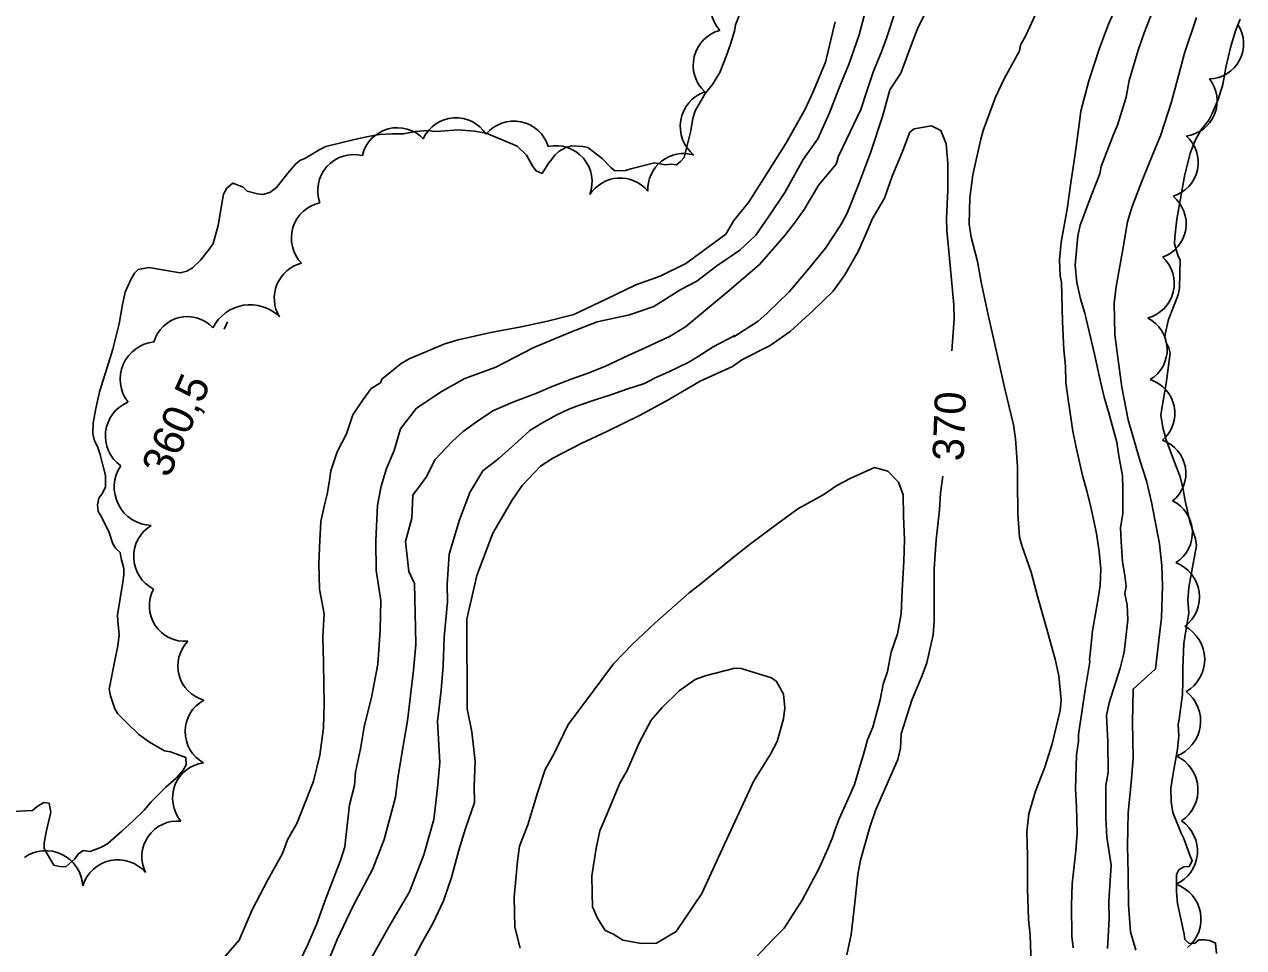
# Model space of a CAD drawing. Extents: x 287698 to 290158, y 5234163 to 5237182.
# Drawn here: x 288524.6 to 288641.9, y 5235240.4 to 5235329.1 of the extents above; entities that cross this region are included whole.
import ezdxf

# ---------------------------------------------------------------- set-up
doc = ezdxf.new("R2010")
doc.units = 0
for name, color, linetype in [('Niveau 1', 7, 'Continuous'), ('Niveau 2', 7, 'Continuous'), ('Niveau 3', 7, 'Continuous'), ('Niveau 4', 7, 'Continuous'), ('Niveau 44', 7, 'Continuous')]:
    doc.layers.add(name, color=color, linetype=linetype)

msp = doc.modelspace()

# ---------------------------------------------------------------- linework, layer by layer
at = {"layer": 'Niveau 1'}
for points in [[(288561.91, 5235239.04), (288562.8, 5235240.76), (288563.94, 5235242.74), (288564.94, 5235244.85), (288565.69, 5235247.08), (288566.42, 5235249.72), (288567.04, 5235251.82), (288567.9, 5235254.32), (288567.87, 5235255.89), (288567.97, 5235258.24), (288567.64, 5235261.11), (288567.21, 5235263.33), (288567.17, 5235271.95), (288568.14, 5235276.15), (288569.69, 5235280.2), (288571.56, 5235283.44), (288572.49, 5235284.79), (288574.26, 5235286.66), (288575.45, 5235287.42), (288578.19, 5235288.84), (288580.65, 5235290), (288583.79, 5235291.53), (288586.44, 5235292.98), (288589.63, 5235294.83), (288592.74, 5235296.23), (288593.65, 5235296.89), (288596.38, 5235298.26), (288598.31, 5235299.6), (288600.49, 5235301.61), (288602.43, 5235303.48), (288603.57, 5235305.07), (288604.83, 5235307.31), (288605.47, 5235308.76), (288606.21, 5235310.47), (288607.36, 5235312.45), (288608.1, 5235314.56), (288609.1, 5235316.94), (288609.81, 5235318.77), (288610.23, 5235319.12), (288611.91, 5235319.4), (288612.8, 5235318.95), (288613.3, 5235317.67), (288613.47, 5235315.81), (288613.46, 5235313.21), (288613.34, 5235310.49), (288613.38, 5235309.32), (288613.69, 5235305.97), (288614.05, 5235302.18), (288614.09, 5235300.84), (288613.85, 5235297.76)], [(288612.99, 5235285.68), (288612.76, 5235284.05), (288612.66, 5235282.47), (288612.33, 5235279.58), (288612.16, 5235276.78), (288612.16, 5235275.19), (288612.15, 5235271.76), (288612.06, 5235270.45), (288611.45, 5235267.75), (288611, 5235266.52), (288610, 5235264.15), (288608.98, 5235260.9), (288608.91, 5235259.54), (288608.65, 5235258.43), (288607.73, 5235256.32), (288606.52, 5235253.55), (288605.95, 5235251.95), (288605.06, 5235248.77), (288604.81, 5235247.37), (288604.51, 5235244.65), (288604.18, 5235241.62), (288603.75, 5235239.66)]]:
    msp.add_lwpolyline(points, dxfattribs=at)
at = {"layer": 'Niveau 2'}
for points in [[(288635.82, 5235348.16), (288635.44, 5235346.6), (288634.77, 5235343.73), (288634.07, 5235340.99), (288633.69, 5235340.04), (288632.52, 5235337.37), (288631.44, 5235334.9), (288630.05, 5235331.71), (288628.93, 5235329.16), (288628.08, 5235326.87), (288627.04, 5235323.71), (288626.27, 5235320.82), (288626.08, 5235319.31), (288625.72, 5235316.7), (288625.32, 5235313.9), (288624.95, 5235311.38), (288624.38, 5235308.2), (288624.23, 5235306.49), (288624.29, 5235304.97), (288624.4, 5235304.35)], [(288550.47, 5235237.71), (288551.84, 5235240.6), (288552.71, 5235242.57), (288553.59, 5235245.07), (288555.05, 5235248.84), (288555.43, 5235250.03), (288555.54, 5235250.94), (288555.87, 5235254.09), (288556.36, 5235255.93), (288556.46, 5235257.24), (288556.95, 5235259.47), (288557.3, 5235261.57), (288558.02, 5235264.58), (288558.62, 5235267.6), (288558.82, 5235270.88), (288558.9, 5235273.75), (288558.45, 5235276.61), (288558.4, 5235279.49), (288558.59, 5235282.9), (288558.94, 5235284.73), (288559.44, 5235286.43), (288560.19, 5235288.15), (288560.8, 5235290.25), (288562.33, 5235292.24), (288564.79, 5235293.86), (288566.99, 5235295.08), (288569.98, 5235296.18), (288573.61, 5235298.08), (288575.94, 5235299.04), (288577.24, 5235299.59), (288579.71, 5235300.55), (288582.83, 5235301.21), (288585.18, 5235302.03), (288587.76, 5235303.65), (288589.31, 5235304.46), (288591.25, 5235305.94), (288593.45, 5235307.42), (288594.99, 5235308.88), (288596.27, 5235310.74), (288597.79, 5235312.99), (288599.56, 5235316.16), (288600.96, 5235318.15), (288602.09, 5235320.65), (288602.96, 5235322.89), (288603.97, 5235325.4), (288604.95, 5235328.16), (288605.93, 5235331.97)], [(288610.54, 5235328.72), (288611.73, 5235331.14)], [(288633.75, 5235331.89), (288632.37, 5235328.33), (288631.8, 5235326.66), (288630.92, 5235323.74), (288630.63, 5235322.15), (288629.8, 5235319.45), (288629.4, 5235318.56), (288628.23, 5235315.49), (288628.09, 5235314.77), (288627.33, 5235312.82), (288626.22, 5235309.83), (288625.97, 5235308.8), (288625.73, 5235305.99), (288625.9, 5235304.33), (288626.23, 5235302.74), (288626.67, 5235301.36)], [(288553.43, 5235238.09), (288554.68, 5235241.12), (288556.19, 5235244.29), (288558.08, 5235247.86), (288559.21, 5235250.75), (288560.31, 5235254.82), (288560.54, 5235256.66), (288561, 5235259.55), (288561.47, 5235262.17), (288562.04, 5235267.02), (288562.25, 5235269.5), (288562.22, 5235271.07), (288562.14, 5235275.38), (288561.59, 5235276.54), (288561.28, 5235279.42), (288561.88, 5235281.65), (288561.97, 5235283.87), (288563.25, 5235285.6), (288564.13, 5235287.31), (288565.8, 5235289.05), (288566.83, 5235289.98), (288568.12, 5235290.92), (288569.67, 5235291.99), (288571.61, 5235292.82), (288573.83, 5235293.64), (288575.39, 5235294.32), (288577.2, 5235295.02), (288578.76, 5235295.57), (288580.45, 5235296.25), (288582.78, 5235297.35), (288584.34, 5235298.03), (288586.68, 5235299.12), (288588.23, 5235300.06), (288590.16, 5235301.67), (288592.22, 5235303.41), (288595.31, 5235306.02), (288596.46, 5235307.35), (288597.74, 5235308.81), (288598.76, 5235310.14), (288599.65, 5235311.33), (288601.05, 5235313.71), (288602.71, 5235315.7), (288602.96, 5235316.49), (288603.71, 5235318.07), (288605.09, 5235320.97), (288605.72, 5235322.81), (288606.33, 5235324.66), (288607.09, 5235326.5), (288607.58, 5235327.82), (288608.44, 5235330.45)], [(288621.89, 5235330.03), (288621.01, 5235328.14), (288620.47, 5235327.14), (288620.38, 5235326.61), (288619.98, 5235325.9)], [(288542.58, 5235237.94), (288545.26, 5235241.08), (288546.52, 5235243.97), (288548.03, 5235246.87), (288549.42, 5235249.39), (288549.92, 5235250.7), (288550.81, 5235252.29), (288551.8, 5235254.79), (288552.43, 5235256.37), (288553.03, 5235258.87), (288553.37, 5235261.49), (288553.45, 5235263.84), (288553.42, 5235265.67), (288553.38, 5235267.76), (288553.33, 5235270.24), (288553.43, 5235272.46), (288552.98, 5235274.82), (288552.94, 5235277.3), (288553.02, 5235279.52), (288553.12, 5235281.35), (288553.49, 5235282.93), (288553.73, 5235283.97), (288553.96, 5235285.29), (288554.08, 5235286.2), (288554.7, 5235288.04), (288555.58, 5235289.76), (288556.2, 5235291.6), (288557.21, 5235293.06), (288557.98, 5235294.12), (288558.88, 5235294.67), (288558.99, 5235295.02), (288560.84, 5235296.52), (288561.63, 5235296.97), (288565.07, 5235298.44), (288566.34, 5235298.81), (288569.5, 5235299.5), (288572.39, 5235300.06), (288574.94, 5235300.6), (288577.48, 5235301.26), (288580.59, 5235302.72), (288583.44, 5235304.09), (288585.77, 5235304.92), (288588.24, 5235306.14), (288589.92, 5235307.36), (288592.11, 5235308.96), (288592.86, 5235310.28), (288594.27, 5235312.01), (288595.8, 5235314.39), (288597.87, 5235317.68), (288599.73, 5235321), (288600.46, 5235322.6), (288601.7, 5235325.52), (288602.64, 5235329.4)], [(288557.99, 5235239.36), (288559.63, 5235242.27), (288561.66, 5235245.7), (288563.03, 5235249.26), (288564.01, 5235252.67), (288564.34, 5235255.69), (288564.56, 5235258.17), (288564.35, 5235262.09), (288564.69, 5235265.11), (288564.91, 5235267.46), (288564.99, 5235270.21), (288565.31, 5235273.61), (288565.28, 5235275.31), (288565.48, 5235278.19), (288566.47, 5235281.48), (288567.47, 5235284.11), (288568.73, 5235286.22), (288570.28, 5235287.43), (288572.08, 5235289.04), (288573.24, 5235290.1), (288574.4, 5235290.78), (288575.83, 5235291.59), (288577, 5235292.13), (288578.03, 5235292.54), (288579.72, 5235293.11), (288581.02, 5235293.52), (288582.58, 5235294.07), (288584.27, 5235294.62), (288585.31, 5235295.17), (288586.61, 5235295.72), (288588.55, 5235296.67), (288589.45, 5235297.21), (288590.88, 5235298.15), (288592.96, 5235299.24), (288592.88, 5235299.09), (288595.23, 5235300.61), (288596.08, 5235301.39), (288598.19, 5235303.44), (288599.96, 5235305.51), (288601.68, 5235307.63), (288603.18, 5235309.88), (288603.77, 5235311), (288604.97, 5235313.96), (288606.05, 5235316.88), (288607.17, 5235320.29), (288607.88, 5235322.86), (288608.96, 5235324.45), (288610.07, 5235327.48), (288610.54, 5235328.72)], [(288637.41, 5235329.82), (288636.25, 5235326.39), (288635.7, 5235324.32), (288634.99, 5235321.7), (288633.95, 5235318.42), (288633.2, 5235316.66), (288632.1, 5235313.98), (288631.2, 5235311.62), (288630.77, 5235310.17), (288630.32, 5235307.49), (288629.66, 5235303.95), (288629.49, 5235302.34), (288629.55, 5235299.33), (288629.78, 5235297.58), (288630.2, 5235294.26), (288630.84, 5235291.11), (288631.95, 5235287.22), (288632.58, 5235285.25), (288633.07, 5235283.2), (288633.85, 5235279.18), (288634.08, 5235277.07)], [(288619.98, 5235325.9), (288618.88, 5235323.93), (288618.07, 5235322.16), (288616.86, 5235318.96), (288616.6, 5235317.98), (288615.89, 5235314.69), (288615.59, 5235312.48)], [(288615.59, 5235312.48), (288615.52, 5235309.97), (288615.71, 5235308.69), (288616.31, 5235306.34), (288616.69, 5235304.36), (288617.36, 5235301.22), (288618.17, 5235297.54), (288618.94, 5235294.09), (288619.8, 5235290.62), (288619.97, 5235289.28), (288620.17, 5235286.62), (288620.17, 5235285.2), (288620.21, 5235282.04), (288620.37, 5235279.83), (288620.63, 5235278.93), (288621.5, 5235276.46), (288622.14, 5235274.01), (288622.93, 5235271.21), (288623.81, 5235268.09), (288624.14, 5235266.48), (288624.37, 5235264.14), (288624.27, 5235263.16), (288623.52, 5235259.95), (288622.8, 5235257.69), (288621.9, 5235255.41), (288621.28, 5235253.23), (288621.08, 5235251.5), (288621.14, 5235249.23), (288621.15, 5235245.99), (288621.22, 5235243.06), (288621.38, 5235241.53), (288621.48, 5235238.81)], [(288624.4, 5235304.35), (288624.52, 5235300.58), (288624.64, 5235297.86), (288624.79, 5235296.29), (288624.82, 5235294.72), (288625.04, 5235293.08), (288625.51, 5235290.01), (288625.79, 5235288.6), (288626.43, 5235285.76), (288626.86, 5235284.27), (288627.27, 5235282.59), (288627.78, 5235280.17), (288628.05, 5235278.45), (288628.2, 5235276.78), (288628.14, 5235275.19), (288627.9, 5235273.73), (288627.39, 5235270.81), (288627.18, 5235268.61), (288627.11, 5235268.1), (288627.14, 5235267.84)], [(288626.67, 5235301.36), (288627.6, 5235297.44), (288628.06, 5235295.23), (288628.53, 5235293.28), (288628.93, 5235291.87), (288629.72, 5235288.96), (288629.93, 5235287.65), (288630.28, 5235285.74), (288630.32, 5235284.47), (288630.31, 5235282.06), (288630.1, 5235280.75), (288630.16, 5235279.4), (288630.29, 5235277.47), (288630.5, 5235276.15), (288630.62, 5235275.12), (288630.5, 5235274.41), (288630.68, 5235273.61)], [(288572.3, 5235240.28), (288571.78, 5235242.33), (288571.73, 5235245.19), (288572.06, 5235248.67), (288572.24, 5235250.1), (288573.03, 5235252.16), (288573.99, 5235255.23), (288574.7, 5235257.47), (288575.55, 5235258.95), (288576.94, 5235261.82), (288578.51, 5235263.9), (288581.3, 5235267.64), (288583.09, 5235269.51), (288585.27, 5235271.56), (288588.57, 5235274.46), (288589.72, 5235275.36), (288593.12, 5235278.12), (288594.47, 5235279.2), (288596.37, 5235280.59), (288599.03, 5235282.54), (288601.54, 5235283.93), (288602.79, 5235284.81), (288604.07, 5235285.47), (288606.41, 5235286.53), (288607.68, 5235286.18), (288608.73, 5235285.12), (288609.16, 5235283.9), (288609.19, 5235281.86), (288609.29, 5235279.59), (288609.22, 5235277.49), (288609.06, 5235274.74), (288608.97, 5235272.46), (288608.62, 5235270.53), (288608.03, 5235268.76), (288607.65, 5235266.92), (288607.26, 5235265.69), (288606.95, 5235264.19), (288606.26, 5235261.55), (288605.74, 5235260.35), (288605.35, 5235258.91), (288604.97, 5235257.67), (288604.48, 5235256.04), (288603.88, 5235254.66), (288603.58, 5235254.02), (288603.02, 5235252.73), (288602.63, 5235251.7), (288602.38, 5235250.95), (288601.91, 5235249.85), (288601.07, 5235247.99), (288599.44, 5235244.9), (288597.71, 5235242.21), (288596.67, 5235241.17), (288592.57, 5235236.86)], [(288634.08, 5235277.07), (288634.12, 5235275.11), (288634.04, 5235272.06), (288633.84, 5235270.47), (288633.45, 5235267.17), (288631.3, 5235265.22), (288631.25, 5235262.02), (288631.32, 5235258.58), (288631.12, 5235256.2), (288630.82, 5235253.36), (288630.76, 5235250.15), (288630.81, 5235247.43), (288630.87, 5235244.47), (288631.04, 5235241.86), (288631.55, 5235240.1)], [(288630.68, 5235273.61), (288630.72, 5235273.32), (288630.78, 5235271.87), (288630.43, 5235268.78), (288630.05, 5235267.24), (288628.99, 5235263.9), (288628.75, 5235262.69), (288628.88, 5235260.18), (288628.89, 5235257.2), (288628.68, 5235255.95), (288628.66, 5235252.82), (288628.78, 5235250.98), (288629.2, 5235248.28), (288628.97, 5235244.79), (288629, 5235243.13), (288628.84, 5235240.25)], [(288627.14, 5235267.84), (288626.68, 5235265.13), (288626.05, 5235260.85), (288626.04, 5235260.18), (288625.84, 5235258.9), (288625.75, 5235255.6), (288625.84, 5235253.92), (288625.92, 5235251.37), (288625.8, 5235249.67), (288625.44, 5235246.49), (288625.38, 5235244.41), (288625.41, 5235241.45), (288625.52, 5235240.34)], [(288591.59, 5235249.48), (288589.78, 5235245.54), (288587.33, 5235241.9), (288585.44, 5235240.78), (288584, 5235240.75), (288582.2, 5235241.08), (288581.23, 5235241.66), (288580.5, 5235242.01), (288579.76, 5235243.19), (288579.26, 5235244.26), (288579.23, 5235245.57), (288579.2, 5235247.25), (288579.63, 5235249.9), (288579.96, 5235251.59), (288580.65, 5235253.15), (288581.91, 5235256.18), (288582.6, 5235257.39), (288583.75, 5235260.04), (288584.9, 5235262.23), (288585.96, 5235263.45), (288587.6, 5235265.04), (288589.16, 5235266.13), (288590.11, 5235266.48), (288592.98, 5235267.23), (288593.59, 5235267.2), (288596.51, 5235266.31), (288596.98, 5235265.95), (288597.64, 5235264.73), (288597.79, 5235263.41), (288597.66, 5235262.35), (288597.03, 5235260.18), (288596.4, 5235258.97), (288594.76, 5235256.34), (288591.59, 5235249.48)]]:
    msp.add_lwpolyline(points, dxfattribs=at)
at = {"layer": 'Niveau 3'}
msp.add_line((288543.82, 5235299.82), (288544.14, 5235300.55), dxfattribs=at)
at = {"layer": 'Niveau 4'}
for points in [[(288593.44, 5235330.17), (288593.03, 5235329.12), (288592.93, 5235328.51), (288592.56, 5235327.24), (288592.17, 5235326.17), (288591.51, 5235324.52), (288590.82, 5235323.38), (288590.1, 5235322.51), (288589.86, 5235322.05), (288589.16, 5235320.85), (288588.93, 5235320.1), (288588.7, 5235318.8), (288588.1, 5235316.35), (288587.75, 5235315.96), (288587.35, 5235315.65), (288586.83, 5235315.7), (288586.29, 5235315.65), (288585.74, 5235315.75), (288585.25, 5235315.83)], [(288636.57, 5235273.78), (288636.68, 5235275), (288636.87, 5235276.07), (288637.39, 5235279.04), (288637.32, 5235279.66), (288637.14, 5235280.14), (288636.76, 5235281.35), (288636.32, 5235283.31), (288636.1, 5235284.61), (288635.79, 5235285.72), (288635.38, 5235286.77), (288634.49, 5235289.18), (288634.15, 5235290.38), (288633.97, 5235291.57), (288634.07, 5235292.22), (288634.49, 5235294.62), (288634.88, 5235297.52), (288634.75, 5235298.03), (288634.47, 5235298.54), (288634.36, 5235299.05), (288634.46, 5235299.64), (288634.72, 5235300.75), (288635.2, 5235301.99), (288635.65, 5235303.15), (288635.76, 5235303.78), (288635.83, 5235306.47), (288635.61, 5235306.95), (288635.28, 5235308.05), (288635.31, 5235308.69), (288635.51, 5235310.42), (288635.73, 5235311.67), (288636.26, 5235314.56), (288636.8, 5235316.78), (288637.27, 5235317.97), (288637.83, 5235318.97), (288638.59, 5235319.95), (288638.91, 5235320.57), (288639.49, 5235321.93), (288639.93, 5235323.37), (288640.21, 5235324.99), (288640.66, 5235326.94), (288641.16, 5235328.54), (288641.59, 5235329.66)], [(288585.25, 5235315.83), (288582.95, 5235315.26), (288582.46, 5235315.09), (288581.41, 5235315.05), (288581.03, 5235315.38), (288580.2, 5235316.24), (288578.83, 5235317.31), (288578.33, 5235317.4), (288577.29, 5235317.48), (288576.69, 5235317.3), (288576.06, 5235316.95), (288575.67, 5235316.59), (288575, 5235315.73), (288574.41, 5235314.82), (288573.84, 5235315.08), (288573.53, 5235315.48), (288572.93, 5235316.57), (288572.03, 5235317.44), (288571.33, 5235317.74), (288569.02, 5235318.68), (288567.92, 5235318.89), (288566.35, 5235319), (288564.68, 5235318.87), (288564.09, 5235318.84), (288563.41, 5235318.93), (288562.22, 5235318.86), (288561.09, 5235318.63), (288560.03, 5235318.62), (288558.78, 5235318.55), (288557.52, 5235318.35), (288556.23, 5235318.05), (288553.6, 5235317.39), (288553.04, 5235317.11), (288551.57, 5235316.25), (288551.11, 5235316.05), (288550.68, 5235315.7), (288549.94, 5235314.83), (288548.86, 5235313.46), (288548.21, 5235312.98), (288547.53, 5235312.8), (288547.03, 5235312.85), (288546.02, 5235313.11), (288545.66, 5235313.49), (288544.65, 5235313.89), (288544.06, 5235313.41), (288543.77, 5235312.81), (288543.66, 5235312.26), (288543.23, 5235309.82), (288542.76, 5235308.08), (288542.42, 5235307.57), (288541.54, 5235306.46), (288540.78, 5235305.72), (288540.23, 5235305.41), (288539.58, 5235305.25), (288539.02, 5235305.34), (288536.58, 5235305.77), (288535.53, 5235305.59), (288535.18, 5235305.21), (288534.82, 5235304.62), (288534.29, 5235303.39), (288534.03, 5235302.22), (288533.7, 5235300.35), (288533.1, 5235297.92), (288532.72, 5235296.65), (288531.83, 5235293.82), (288531.47, 5235292.21), (288531.22, 5235290.82), (288531.18, 5235289.77), (288531.33, 5235289.09), (288531.64, 5235288.55), (288531.86, 5235287.88), (288532.41, 5235285.77), (288532.4, 5235284.68), (288532.1, 5235284.06), (288531.76, 5235283.59), (288531.62, 5235282.93), (288531.69, 5235282.31), (288532.01, 5235281.78), (288532.74, 5235280.27), (288533.11, 5235279.19), (288533.4, 5235278.75), (288533.8, 5235278.36), (288533.9, 5235277.79), (288534.16, 5235276.81), (288534.17, 5235276.2), (288534.05, 5235275.49), (288533.54, 5235272.37), (288533.57, 5235271.74), (288533.7, 5235270.44), (288533.58, 5235269.38), (288533.29, 5235267.97), (288532.74, 5235265.22), (288532.87, 5235264.57), (288533.28, 5235263.32), (288533.6, 5235262.84), (288534.41, 5235261.99), (288535.6, 5235260.84), (288536.63, 5235260.11), (288538.09, 5235259.28), (288538.64, 5235259.17), (288540.13, 5235258.62)], [(288639.32, 5235239.77), (288639.24, 5235240.78), (288638.69, 5235241.02), (288638.18, 5235241.11), (288637.63, 5235241.1), (288637.22, 5235240.75), (288636.65, 5235240.77), (288636.29, 5235241.14), (288636.22, 5235241.64), (288635.86, 5235243.28), (288635.56, 5235244.58), (288635.47, 5235245.71), (288635.48, 5235247.37), (288635.69, 5235247.84), (288636.18, 5235248.12), (288636.7, 5235248.15), (288637, 5235248.71), (288636.75, 5235249.24), (288636.18, 5235250.84), (288635.94, 5235251.37), (288635.11, 5235253.33), (288634.95, 5235254.37), (288634.94, 5235255.67), (288635.13, 5235256.9), (288635.58, 5235259.44), (288635.7, 5235260.72), (288635.64, 5235261.82), (288635.72, 5235262.32), (288636.04, 5235264.7), (288636.1, 5235265.97), (288636.09, 5235267.27), (288636.17, 5235269.59), (288636.39, 5235270.81), (288636.65, 5235272.53), (288636.57, 5235273.78)], [(288540.13, 5235258.62), (288540.17, 5235257.94), (288539.88, 5235257.43), (288539.19, 5235256.65), (288538.2, 5235255.77), (288536.78, 5235254.36), (288536.11, 5235253.56), (288535.1, 5235252.56), (288533.98, 5235251.54), (288532.62, 5235250.36), (288532.01, 5235250.02), (288530.92, 5235249.58), (288530.26, 5235249.68), (288529.79, 5235249.38), (288529.46, 5235248.89), (288528.57, 5235248.13), (288527.97, 5235248.15), (288527.42, 5235248.29), (288527.12, 5235248.75), (288526.48, 5235249.88), (288526.5, 5235250.42), (288526.71, 5235251.61), (288527.12, 5235253.38), (288526.97, 5235254.24), (288526.47, 5235254.31), (288525.82, 5235253.93), (288525.36, 5235253.53), (288524.71, 5235253.52), (288523.51, 5235253.43)]]:
    msp.add_lwpolyline(points, dxfattribs=at)
at = {"layer": 'Niveau 44'}
for centre, radius, start, end in [((288594.13, 5235330.95), 3.52, 100.7485, 222.4406), ((288638.56, 5235327.29), 3.38, 271.4388, 33.351), ((288592.44, 5235325.22), 3.48, 105.1791, 227.2956), ((288636, 5235321.78), 3.39, 276.964, 38.8227), ((288591.23, 5235319.33), 3.52, 109.0199, 231.1688), ((288566.12, 5235316.71), 3.46, 32.7684, 154.4435), ((288634.18, 5235315.87), 3.39, 286.7005, 48.7863), ((288633.01, 5235309.97), 3.4, 289.5043, 51.1274), ((288631.82, 5235304.23), 3.44, 285.1819, 47.3455), ((288552.11, 5235302.81), 3.47, 104.2491, 211.0517), ((288546.32, 5235298.2), 3.99, 44.9617, 153.8867), ((288540.27, 5235297.7), 3.34, 42.5508, 164.3796), ((288537.41, 5235295.02), 3.6, 95.7194, 217.7402), ((288535.91, 5235289.56), 3.52, 112.5308, 234.419), ((288632.99, 5235285.96), 3.39, 308.6108, 70.4091), ((288633.61, 5235280.26), 3.4, 302.2743, 63.9034), ((288634.15, 5235274.08), 3.54, 306.926, 68.8628), ((288540.03, 5235273.22), 3.41, 151.7131, 274.9596), ((288634.6, 5235268.08), 3.59, 300.2345, 62.141), ((288542.77, 5235267.44), 3.41, 135.7555, 254.5853), ((288634.21, 5235262.14), 3.59, 290.3156, 52.2615), ((288543.51, 5235261.13), 3.45, 118.5904, 240.6508), ((288633.96, 5235255.52), 3.59, 303.6375, 65.3282), ((288542.29, 5235254.72), 3.44, 97.9239, 219.7134), ((288539.33, 5235249.1), 3.43, 84.7174, 206.4722), ((288634, 5235249.63), 3.5, 294.2163, 56.0229), ((288526.65, 5235246.1), 3.57, 3.2398, 125.2729), ((288533.59, 5235245.25), 3.54, 41.0348, 162.6757), ((288634.29, 5235243.09), 3.54, 309.3322, 71.145)]:
    msp.add_arc(centre, radius, start, end, dxfattribs=at)
for centre, major_axis, ratio, start_param, end_param in [((288560.49, 5235315.75), (-3.35, -0.89), 0.998779, 3.635945, 5.788833), ((288571.71, 5235316.4), (-3.39, 0.67), 0.999463, 3.631093, 5.793685), ((288575.76, 5235314.01), (-2.27, 2.63), 0.999985, 3.638025, 5.786753), ((288556.29, 5235313.16), (-3.19, -1.36), 0.998726, 4.071323, 6.2253), ((288588.05, 5235313.26), (-2.44, -2.47), 0.998773, 3.63747, 5.530156), ((288581.92, 5235310.91), (-3.45, 0.27), 0.999038, 3.91134, 5.790649), ((288553.76, 5235308.59), (-2.99, 1.77), 0.999929, 5.458487, 7.584278), ((288631.19, 5235297.88), (3.39, 0.13), 0.999977, 5.220901, 7.348539), ((288631.92, 5235291.74), (3.33, 0.68), 0.999949, 5.218502, 7.344164), ((288536.93, 5235284.64), (-3.29, -1.68), 0.999981, 5.221507, 7.34497), ((288538.61, 5235277.96), (-3.5, -0.14), 0.999979, 5.220093, 7.34693)]:
    msp.add_ellipse(centre, major_axis=major_axis, ratio=ratio, start_param=start_param, end_param=end_param, dxfattribs=at)

# ---------------------------------------------------------------- texts
at = {"layer": 'Niveau 1'}
msp.add_text('370', height=3, rotation=87.8323, dxfattribs=at).set_placement((288614.98, 5235287.1))
at = {"layer": 'Niveau 3'}
msp.add_text('360,5', height=3, rotation=66.1217, dxfattribs=at).set_placement((288538.5, 5235285.44))

doc.saveas('drawing.dxf')
